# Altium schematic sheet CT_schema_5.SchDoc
size 298 x 247 mm
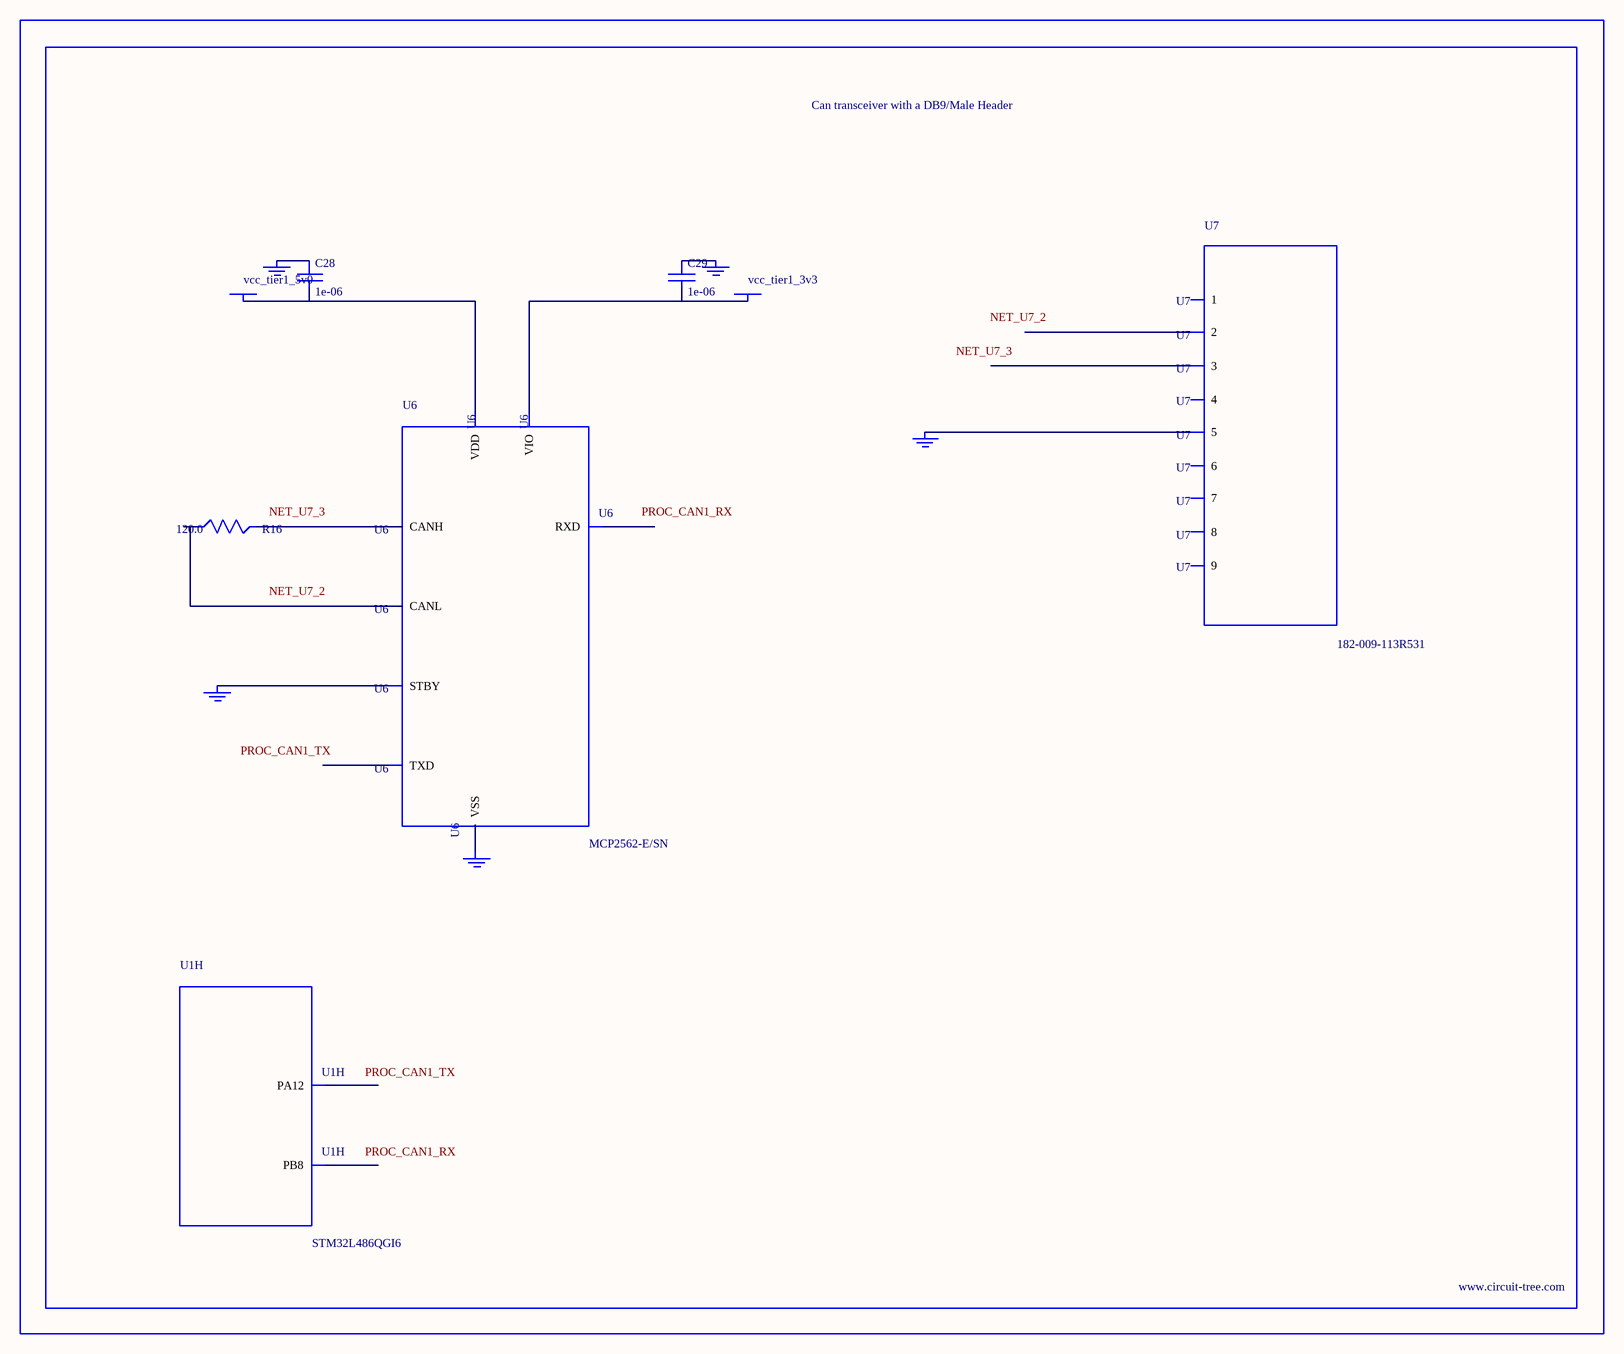
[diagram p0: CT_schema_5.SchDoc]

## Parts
BORDER4  (no value)
C28  1e-06  [C0603]
C29  1e-06  [C0603]
GND_INSTANCE_4_0  (no value)
GND_INSTANCE_4_1  (no value)
GND_INSTANCE_4_2  (no value)
GND_INSTANCE_4_3  (no value)
GND_INSTANCE_4_4  (no value)
POWER_INSTANCE_4_0  vcc_tier1_5v0
POWER_INSTANCE_4_1  vcc_tier1_3v3
R16  120.0  [R0603]
U1  STM32L486QGI6  [UFBGA132]  (part H of 13)
U6  MCP2562-E/SN  [SOIC-8]
U7  182-009-113R531  [182-009-MALE]

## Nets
NetC28_1: C28.1 GND_INSTANCE_4_0.0(GND)
NetC28_2: C28.2 POWER_INSTANCE_4_0.0(PWR) U6.3(VDD)
NetC29_1: C29.1 GND_INSTANCE_4_1.0(GND)
NetC29_2: C29.2 POWER_INSTANCE_4_1.0(PWR) U6.5(VIO)
NetGND_INSTANCE_4_2_0: GND_INSTANCE_4_2.0(GND) U6.8(STBY)
NetGND_INSTANCE_4_3_0: GND_INSTANCE_4_3.0(GND) U6.2(VSS)
NetGND_INSTANCE_4_4_0: GND_INSTANCE_4_4.0(GND) U7.5
NetR16_1: R16.1 U6.6(CANL)
NetR16_2: R16.2 U6.7(CANH)

Not connected (* = marked no-connect by the designer): U1 A3(PB8) A12(PA12); U6 1(TXD) 4(RXD); U7 1 2 3 4 6 7 8 9

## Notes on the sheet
- Labels drawn without touching a wire or pin: NET_U7_2, NET_U7_3, PROC_CAN1_RX, PROC_CAN1_TX

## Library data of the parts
BORDER4 = BORDER_PAGE4
C28 C29 = C0603C105K3RACTU
GND_INSTANCE_4_0-GND_INSTANCE_4_4 = GND
POWER_INSTANCE_4_0 POWER_INSTANCE_4_1 = PWR
R16 = RC0603JR-07120RL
